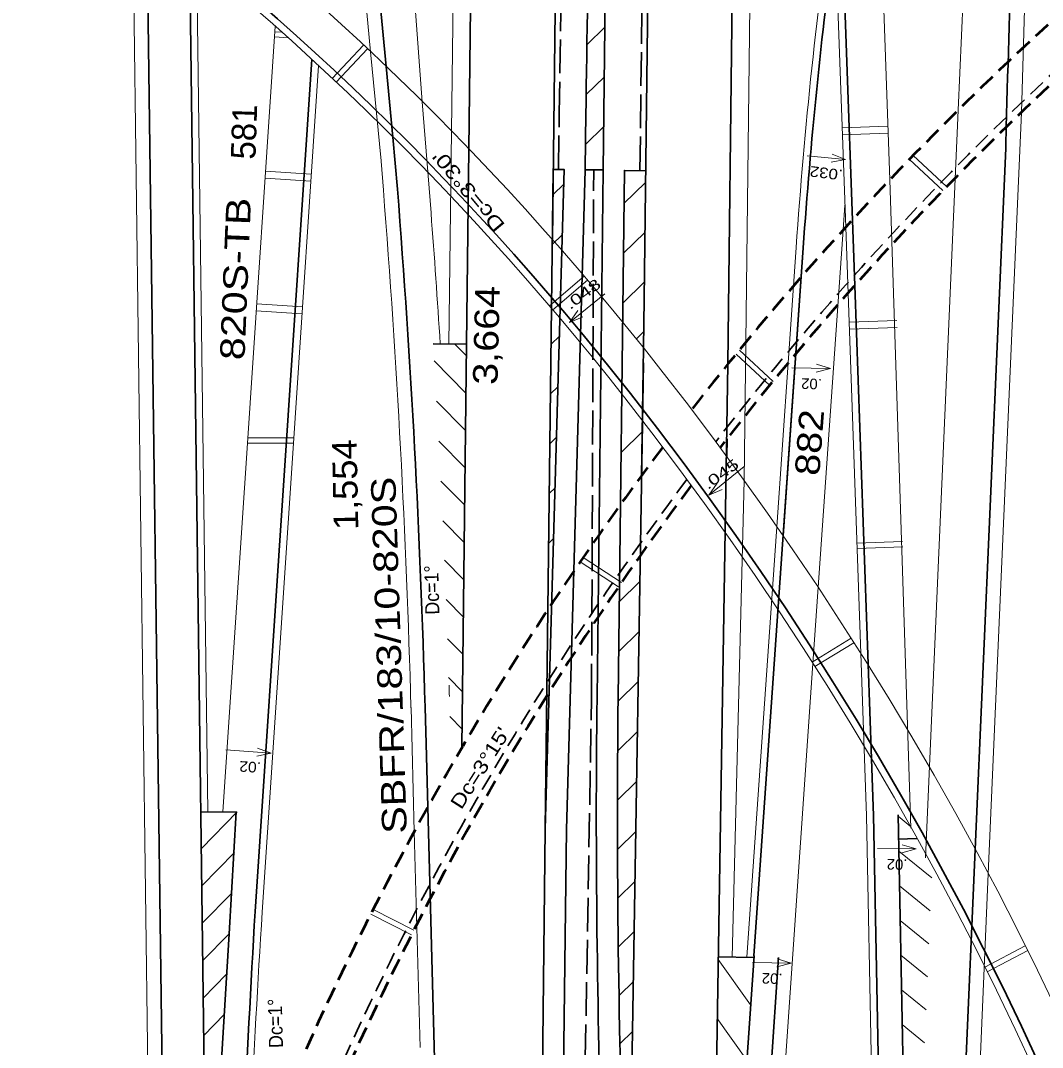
# Model space of a CAD drawing. Extents: x 2354993 to 2372084, y 6966390 to 6990057.
# Drawn here: x 2364175 to 2364756, y 6977227 to 6977811 of the extents above; entities that cross this region are included whole.
import ezdxf

# ---------------------------------------------------------------- set-up
doc = ezdxf.new("R2010")
doc.units = 0
doc.header["$LTSCALE"] = 3.2
doc.linetypes.add('LONG_DASHED', pattern=[7.5, 6, -1.5])
doc.linetypes.add('MEDIUM_DASHED', pattern=[4.5, 3, -1.5])
for name, color, linetype, lineweight in [('11', 7, 'Continuous', 13), ('12', 7, 'Continuous', 13), ('13', 7, 'Continuous', 13), ('17', 7, 'Continuous', 13), ('19', 7, 'Continuous', 13), ('2', 7, 'Continuous', 35), ('30', 7, 'Continuous', 13), ('4', 7, 'Continuous', 13), ('5', 7, 'Continuous', 35), ('6', 7, 'Continuous', 35)]:
    doc.layers.add(name, color=color, linetype=linetype, lineweight=lineweight)

msp = doc.modelspace()

# ---------------------------------------------------------------- linework, layer by layer
at = {"layer": '12'}
for p, q in [((2364639.864, 6977804.901), (2364639.97, 6977801.903)), ((2364369.799, 6977797.053), (2364352.016, 6977778.088)), ((2364371.986, 6977794.999), (2364354.201, 6977776.034)), ((2364679.982, 6977732.147), (2364699.055, 6977714.467)), ((2364682.071, 6977734.301), (2364701.094, 6977716.667)), ((2364643.399, 6977704.963), (2364643.293, 6977707.961)), ((2364495.167, 6977665.762), (2364475.372, 6977648.908)), ((2364497.113, 6977663.48), (2364477.319, 6977646.626)), ((2364581.452, 6977621.46), (2364600.558, 6977603.75)), ((2364583.356, 6977623.785), (2364602.597, 6977605.95)), ((2364304.056, 6977573.955), (2364330.108, 6977573.868)), ((2364676.136, 6977514.999), (2364650.151, 6977514.081)), ((2364676.242, 6977512.001), (2364650.257, 6977511.083)), ((2364514.605, 6977489.152), (2364492.873, 6977503.438)), ((2364516.307, 6977491.623), (2364494.575, 6977505.909)), ((2364646.876, 6977459.976), (2364624.664, 6977446.453)), ((2364648.436, 6977457.414), (2364626.224, 6977443.891)), ((2364398.4, 6977294.133), (2364375.246, 6977305.961)), ((2364397.038, 6977291.46), (2364373.884, 6977303.289)), ((2364745.82, 6977285.312), (2364722.816, 6977273.183)), ((2364747.219, 6977282.658), (2364724.215, 6977270.529))]:
    msp.add_line(p, q, dxfattribs=at)
at = {"layer": '17'}
for p, q in [((2364319.208, 6977801.68), (2364326.875, 6977801.17)), ((2364319.407, 6977804.674), (2364323.251, 6977804.418)), ((2364641.802, 6977750.11), (2364667.787, 6977751.029)), ((2364641.943, 6977746.112), (2364667.929, 6977747.031)), ((2364314.14, 6977725.507), (2364340.082, 6977723.781)), ((2364313.874, 6977721.516), (2364339.817, 6977719.79)), ((2364309.125, 6977650.118), (2364335.067, 6977648.392)), ((2364308.859, 6977646.127), (2364334.801, 6977644.401)), ((2364645.71, 6977639.575), (2364672.789, 6977640.533)), ((2364645.851, 6977635.578), (2364672.931, 6977636.536))]:
    msp.add_line(p, q, dxfattribs=at)
at = {"layer": '19'}
for p, q in [((2364643.753, 6977731.987), (2364635.568, 6977730.535)), ((2364486.81, 6977639.513), (2364491.605, 6977646.303)), ((2364635.114, 6977613.378), (2364627.087, 6977611.218)), ((2364565.952, 6977541.376), (2364570.736, 6977548.173)), ((2364317.267, 6977394.658), (2364309.126, 6977392.982)), ((2364683.737, 6977340.26), (2364675.71, 6977338.1)), ((2364612.746, 6977275.44), (2364604.719, 6977273.28))]:
    msp.add_line(p, q, dxfattribs=at)
for points in [[(2364621.942, 6977734.217), (2364643.753, 6977731.987), (2364636.037, 6977735.064)], [(2364506.883, 6977655.694), (2364486.81, 6977639.513), (2364494.457, 6977642.755)], [(2364613.192, 6977613.698), (2364635.114, 6977613.378), (2364627.159, 6977615.77)], [(2364586.002, 6977557.585), (2364565.952, 6977541.376), (2364573.594, 6977544.629)], [(2364291.557, 6977396.58), (2364317.267, 6977394.658), (2364309.471, 6977397.522)], [(2364661.815, 6977340.58), (2364683.737, 6977340.26), (2364675.782, 6977342.652)], [(2364590.824, 6977275.76), (2364612.746, 6977275.44), (2364604.791, 6977277.832)]]:
    msp.add_lwpolyline(points, dxfattribs=at)
at = {"layer": '2'}
for p, q in [((2364529.276, 6977652.647), (2364533.131, 6977979.184)), ((2364576.847, 6977615.806), (2364580.614, 6977935.024)), ((2364308.187, 6977304.651), (2364340.403, 6977788.872)), ((2364517.997, 6977725.725), (2364530.018, 6977725.62)), ((2364528.831, 6977625.062), (2364529.276, 6977652.647)), ((2364527.657, 6977552.255), (2364528.831, 6977625.062)), ((2364576.225, 6977563.164), (2364576.346, 6977573.406))]:
    msp.add_line(p, q, dxfattribs=at)
msp.add_arc((2372851.201, 6976799.233), 8557.951, 176.61424, 178.30543, dxfattribs=at)
at = {"layer": '30', "lineweight": 25}
msp.add_line((2364514.461, 6977426.009), (2364514.46, 6977426.009), dxfattribs=at)
at = {"layer": '4'}
for p, q in [((2364643.359, 6977706.079), (2364642.388, 6977692.091)), ((2364642.388, 6977692.091), (2364625.192, 6977445.625)), ((2364592.679, 6976978.427), (2364625.192, 6977445.625))]:
    msp.add_line(p, q, dxfattribs=at)
msp.add_lwpolyline([(2364586.065, 6977549.629), (2364586.993, 6977628.202), (2364591.132, 6977978.904)], dxfattribs=at)
at = {"layer": '4', "lineweight": 35}
for centre, radius, start, end in [((2376431.6, 6977432.787), 11700.93, 177.32697, 178.44412), ((2372282.953, 6977585.958), 7549.762, 178.75127, 178.8426)]:
    msp.add_arc(centre, radius, start, end, dxfattribs=at)
at = {"layer": '4'}
msp.add_arc((2358034.476, 6977244.063), 6386.72, 1.64074, 1.69802, dxfattribs=at)
at = {"layer": '5', "lineweight": 13}
for p, q in [((2364419.746, 6977748.182), (2364423.405, 6978053.282)), ((2364743.625, 6977758.845), (2364752.236, 6978048.996)), ((2364403.156, 6977764.879), (2364386.841, 6977979.677)), ((2364643.799, 6977693.64), (2364633.713, 6977978.844)), ((2364707.646, 6977760.094), (2364717.285, 6977978.562)), ((2364360.096, 6977935.765), (2364373.781, 6977793.307)), ((2364250.238, 6976989.323), (2364238.582, 6977875.031)), ((2364281.346, 6977361.167), (2364274.986, 6977844.567)), ((2364303.858, 6977570.955), (2364319.606, 6977807.665)), ((2364373.781, 6977793.307), (2364379.731, 6977731.359)), ((2364408.143, 6977701.711), (2364403.156, 6977764.879)), ((2364689.178, 6977335.168), (2364707.646, 6977760.094)), ((2364724.81, 6977326.163), (2364743.625, 6977758.845)), ((2364418.296, 6977627.191), (2364419.746, 6977748.182)), ((2364381.056, 6977714.653), (2364379.753, 6977731.087)), ((2364652.368, 6977451.315), (2364643.799, 6977693.64)), ((2364428.221, 6977620.416), (2364421.64, 6977627.146)), ((2364427.982, 6977599.204), (2364409.955, 6977617.639)), ((2364427.745, 6977577.993), (2364411.325, 6977594.785)), ((2364289.908, 6977361.289), (2364303.857, 6977570.955)), ((2364303.857, 6977570.955), (2364329.908, 6977570.868)), ((2364427.507, 6977556.781), (2364412.597, 6977572.029)), ((2364427.27, 6977535.569), (2364413.774, 6977549.372)), ((2364579.253, 6977278.831), (2364586.065, 6977549.629)), ((2364427.033, 6977514.357), (2364414.856, 6977526.81)), ((2364587.627, 6977278.696), (2364604.616, 6977523.417)), ((2364426.796, 6977493.145), (2364415.844, 6977504.344)), ((2364426.558, 6977471.934), (2364416.742, 6977481.97)), ((2364426.319, 6977450.722), (2364417.548, 6977459.692)), ((2364655.632, 6977359.023), (2364652.368, 6977451.315)), ((2364426.082, 6977429.509), (2364418.081, 6977437.691)), ((2364398.641, 6977350.205), (2364396.773, 6977420.626)), ((2364425.844, 6977408.298), (2364418.837, 6977415.464)), ((2364277.618, 6977340.505), (2364297.932, 6977361.405)), ((2364655.625, 6977359.311), (2364666.287, 6976808.765)), ((2364673.637, 6977358.831), (2364680.458, 6977353.235)), ((2364401.898, 6977227.486), (2364398.641, 6977350.205)), ((2364674.019, 6977339.116), (2364692.678, 6977323.807)), ((2364277.898, 6977319.276), (2364296.396, 6977338.304)), ((2364690.072, 6976527.283), (2364724.81, 6977326.163)), ((2364674.401, 6977319.401), (2364691.864, 6977305.074)), ((2364278.176, 6977298.048), (2364294.858, 6977315.206)), ((2364674.782, 6977299.686), (2364691.049, 6977286.34)), ((2364278.456, 6977276.813), (2364293.339, 6977292.123)), ((2364571.23, 6977277.458), (2364589.757, 6977251.624)), ((2364675.164, 6977279.971), (2364690.235, 6977267.607)), ((2364278.735, 6977255.585), (2364291.909, 6977269.136)), ((2364675.546, 6977260.257), (2364689.42, 6977248.873)), ((2364279.015, 6977234.351), (2364290.579, 6977246.246)), ((2364570.688, 6977243.894), (2364587.585, 6977220.334)), ((2364675.928, 6977240.541), (2364688.605, 6977230.139))]:
    msp.add_line(p, q, dxfattribs=at)
at = {"layer": '5'}
for p, q in [((2364648.972, 6977660.539), (2364639.273, 6977934.826)), ((2364246.695, 6977868.679), (2364257.91, 6977015.279)), ((2364280.781, 6977100.108), (2364270.924, 6977849.204)), ((2364496.872, 6977797.492), (2364506.96, 6977807.345)), ((2364386.476, 6977744.802), (2364382.624, 6977784.897)), ((2364496.342, 6977769.018), (2364506.627, 6977779.063)), ((2364496.117, 6977756.969), (2364496.142, 6977759.009)), ((2364495.926, 6977740.656), (2364506.293, 6977750.781)), ((2364389.03, 6977715.284), (2364386.476, 6977744.802)), ((2364428.294, 6977627.07), (2364429.624, 6977738.01)), ((2364717.405, 6977340.009), (2364734.731, 6977738.457)), ((2364485.08, 6977351.259), (2364495.752, 6977726.05)), ((2364502.462, 6977426.131), (2364506.001, 6977726.13)), ((2364514.46, 6977426.009), (2364518, 6977725.988)), ((2364477.475, 6977712.106), (2364483.518, 6977718.009)), ((2364517.776, 6977707.036), (2364530.06, 6977719.034)), ((2364477.002, 6977683.686), (2364482.699, 6977689.251)), ((2364517.443, 6977678.753), (2364529.584, 6977690.612)), ((2364591.636, 6977279.587), (2364619.625, 6977681.868)), ((2364615.452, 6977621.75), (2364619.625, 6977681.866)), ((2364517.109, 6977650.471), (2364529.25, 6977662.329)), ((2364658.49, 6977391.403), (2364648.972, 6977660.539)), ((2364476.335, 6977627.117), (2364481.062, 6977631.734)), ((2364524.88, 6977630.105), (2364528.916, 6977634.047)), ((2364428.294, 6977627.07), (2364409.35, 6977627.283)), ((2364428.294, 6977627.07), (2364425.729, 6977397.952)), ((2364608.26, 6977518.156), (2364615.452, 6977621.75)), ((2364518.585, 6976988.524), (2364528.853, 6977616.591)), ((2364565.082, 6976896.195), (2364576.847, 6977615.806)), ((2364476.001, 6977598.833), (2364480.243, 6977602.976)), ((2364475.668, 6977570.552), (2364479.424, 6977574.221)), ((2364516.108, 6977565.625), (2364528.249, 6977577.482)), ((2364475.334, 6977542.268), (2364478.605, 6977545.463)), ((2364475.001, 6977513.985), (2364477.786, 6977516.706)), ((2364515.106, 6977480.778), (2364526.82, 6977492.219)), ((2364514.773, 6977452.496), (2364526.356, 6977463.809)), ((2364514.44, 6977424.215), (2364525.891, 6977435.399)), ((2364405.509, 6977392.943), (2364404.742, 6977420.845)), ((2364514.297, 6977396.119), (2364525.427, 6977406.99)), ((2364406.277, 6977364.018), (2364405.509, 6977392.943)), ((2364659.63, 6977359.164), (2364658.49, 6977391.403)), ((2364514.27, 6977368.136), (2364524.962, 6977378.58)), ((2364411.249, 6977176.688), (2364406.277, 6977364.018)), ((2364277.347, 6977361.111), (2364297.345, 6977361.394)), ((2364659.624, 6977359.388), (2364670.286, 6976808.842)), ((2364673.621, 6977359.659), (2364679.974, 6977031.633)), ((2364463.051, 6976501.012), (2364473.085, 6977351.601)), ((2364468.806, 6975971.515), (2364485.084, 6977351.459)), ((2364514.242, 6977340.154), (2364524.498, 6977350.169)), ((2364673.484, 6977345.842), (2364684.368, 6977346.22)), ((2364683.134, 6976551.86), (2364717.405, 6977340.009)), ((2364514.283, 6977312.237), (2364524.033, 6977321.76)), ((2364514.717, 6977284.705), (2364523.569, 6977293.35)), ((2364565.082, 6976896.195), (2364591.695, 6977279.547)), ((2364571.254, 6977278.96), (2364591.632, 6977278.632)), ((2364574.032, 6976822.971), (2364605.662, 6977278.577)), ((2364515.151, 6977257.172), (2364523.104, 6977264.94)), ((2364515.585, 6977229.64), (2364522.64, 6977236.53))]:
    msp.add_line(p, q, dxfattribs=at)
at = {"layer": '5', "linetype": 'LONG_DASHED'}
for p, q in [((2364526.874, 6977725.884), (2364528.605, 6977872.51)), ((2364480.631, 6977726.427), (2364480.993, 6977757.146)), ((2364499.337, 6977426.187), (2364500.596, 6977726.327)), ((2364483.383, 6976501.515), (2364499.337, 6977426.187))]:
    msp.add_line(p, q, dxfattribs=at)
at = {"layer": '5'}
for points in [[(2364429.624, 6977738.01), (2364432.519, 6977979.523), (2364433.384, 6978051.518)], [(2364477.172, 6977686.469), (2364480.63, 6977979.361), (2364481.479, 6978051.356)], [(2364496.142, 6977759.009), (2364495.756, 6977726.25), (2364506.002, 6977726.13), (2364507.732, 6977872.751)], [(2364514.46, 6977426.009), (2364518, 6977725.988), (2364514.46, 6977426.009)], [(2364297.345, 6977361.394), (2364293.339, 6977292.123), (2364289.347, 6977223.458), (2364285.358, 6977133.277), (2364282.372, 6976979.158)]]:
    msp.add_lwpolyline(points, dxfattribs=at)
at = {"layer": '5', "lineweight": 13}
for points in [[(2364680.862, 6977352.125), (2364668.863, 6977720.558), (2364659.733, 6977978.756)], [(2364312.181, 6977304.414), (2364329.909, 6977570.868), (2364344.181, 6977785.387)], [(2364604.616, 6977523.417), (2364611.079, 6977616.516), (2364615.635, 6977682.143)]]:
    msp.add_lwpolyline(points, dxfattribs=at)
at = {"layer": '5'}
msp.add_lwpolyline([(2364473.085, 6977351.601), (2364483.757, 6977726.392), (2364477.507, 6977726.466)], close=True, dxfattribs=at)
at = {"layer": '5', "lineweight": 13}
for centre, radius, start, end in [((2363244.672, 6976597.082), 1645.014, 38.12295, 103.3303), ((2363244.672, 6976597.082), 1619.014, 38.12295, 103.3303), ((2363127.192, 6979233.99), 1683.022, 290.12282, 308.67239), ((2363217.727, 6979240.251), 1666, 287.12386, 306.40449), ((2363217.727, 6979240.251), 1692, 268.21361, 306.66787), ((2367491.502, 6977482.494), 2882.789, 171.96478, 176.02877), ((2358691.326, 6977263.63), 5707.578, 1.57563, 4.53232), ((2358691.326, 6977263.605), 5733.578, 3.63624, 4.38227), ((2363030.028, 6976428.641), 1917.859, 350.16881, 38.12295), ((2363030.028, 6976428.641), 1891.859, 350.16881, 38.12295), ((2373046.888, 6976763.367), 8751.449, 176.45552, 178.03092)]:
    msp.add_arc(centre, radius, start, end, dxfattribs=at)
at = {"layer": '5'}
for centre, radius, start, end in [((2363244.672, 6976597.082), 1623.014, 38.12295, 103.3303), ((2370213.297, 6977689.532), 5717.578, 176.62485, 179.32419), ((2363217.727, 6979240.251), 1684, 268.21361, 306.58945), ((2367491.502, 6977482.494), 2878.789, 172.42387, 176.02877), ((2358691.326, 6977263.63), 5715.578, 1.57563, 4.53232), ((2363030.028, 6976428.641), 1895.859, 350.16881, 38.12295), ((2370231.641, 6977358.541), 5729.578, 179.32409, 181.97449), ((2370231.641, 6977358.541), 5717.578, 179.32409, 182.18622)]:
    msp.add_arc(centre, radius, start, end, dxfattribs=at)
at = {"layer": '5', "linetype": 'LONG_DASHED'}
msp.add_arc((2370213.296, 6977689.531), 5732.703, 177.45392, 179.32419, dxfattribs=at)
at = {"layer": '5', "linetype": 'MEDIUM_DASHED', "lineweight": 53}
for centre, radius, start, end in [((2365952.337, 6976500.333), 1770.947, 128.18302, 142.02993), ((2365952.338, 6976500.332), 1744.947, 127.94306, 142.26149), ((2365952.337, 6976500.333), 1770.947, 142.90202, 179.54796), ((2365952.338, 6976500.332), 1744.947, 143.1512, 179.53746)]:
    msp.add_arc(centre, radius, start, end, dxfattribs=at)
at = {"layer": '5', "linetype": 'MEDIUM_DASHED'}
for start, end in [(127.98178, 142.22456), (143.1115, 179.53746)]:
    msp.add_arc((2365952.338, 6976500.332), 1748.947, start, end, dxfattribs=at)
at = {"layer": '6'}
msp.add_line((2364363.907, 6977979.755), (2364382.624, 6977784.897), dxfattribs=at)

# ---------------------------------------------------------------- texts
at = {"layer": '11'}
for s, rotation, width, p in [('.032', 173.117, 1.2, (2364642.366, 6977726.15)), ('.02', 178.117, 1.05, (2364630.296, 6977607.381)), ('.02', 178.117, 1.05, (2364678.919, 6977334.263)), ('.02', 178.117, 1.05, (2364607.928, 6977269.443))]:
    msp.add_text(s, height=6, rotation=rotation, dxfattribs=dict(at, width=width)).set_placement(p)
at = {"layer": '12'}
for s, height, rotation, width, p in [('Dc=1°', 8, 91.467, 0.95, (2364412.928, 6977473.499)), ("Dc=3°15'", 7.999, 57.39, 1.2, (2364425.361, 6977362.211)), ('Dc=1°', 8, 91.467, 0.95, (2364324.054, 6977227.257))]:
    msp.add_text(s, height=height, rotation=rotation, dxfattribs=dict(at, width=width)).set_placement(p)
at = {"layer": '13'}
msp.add_text('581', height=14, rotation=88.06, dxfattribs=at).set_placement((2364308.326, 6977731.886))
for s, rotation, width, p in [('820S-TB', 87.659, 1.25, (2364302.12, 6977617.844)), ('3,664', 88.535, 1.2, (2364445.864, 6977603.886)), ('882', 85.709, 1.2, (2364628.751, 6977552.03)), ('1,554', 91.067, 1.1, (2364366.84, 6977521.589)), ('SBFR/183/10-820S', 91.849, 1.25, (2364394.43, 6977349.116))]:
    msp.add_text(s, height=14, rotation=rotation, dxfattribs=dict(at, width=width)).set_placement(p)
at = {"layer": '17', "width": 1.3}
msp.add_text("Dc=3°30'", height=8, rotation=129.697, dxfattribs=at).set_placement((2364450.601, 6977694.931))
at = {"layer": '19'}
for s, height, rotation, width, p in [('.048', 5.999, 36.73, 1.45, (2364487.191, 6977646.463)), ('.045', 6, 35.983, 1.45, (2364565.45, 6977544.224)), ('.02', 6, 176.461, 1.1, (2364311.68, 6977389.487))]:
    msp.add_text(s, height=height, rotation=rotation, dxfattribs=dict(at, width=width)).set_placement(p)

doc.saveas('drawing.dxf')
